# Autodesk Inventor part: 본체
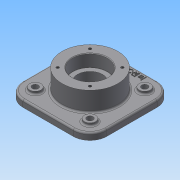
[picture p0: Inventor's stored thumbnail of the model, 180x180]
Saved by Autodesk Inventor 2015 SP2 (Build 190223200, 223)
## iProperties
Created: 2015-07
Part Number: 본체
Material: 일반
Document SubType Name: Modeling
Designer: AMC
Density: 1 g/cm^3
Appearance: 기본값
Author: AMC
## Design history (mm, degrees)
sketch "스케치1"
  geometry: L1 (-75, 75)-(75, 75); L2 (75, 75)-(75, -75); L3 (75, -75)-(-75, -75); L4 (-75, -75)-(-75, 75); L5 (-75, 75)-(75, -75); L6 (75, 75)-(-75, -75); 1 further point
  constraints: 12 end point, 2 midpoint, 2 parallel, 1 horizontal, 1 perpendicular
  dimensions: "d0" = 150 distance of L2.end L3.end; "d1" = 150 distance of L1.end L2.end
extrude "돌출1" new body sketch "스케치1" distance "d2" = 12; taper "d3" = 0 deg
sketch "스케치2"
  geometry: C1 r 50 at (0, 0); 1 further point
  constraints: 1 centre point, 1 coincident
  dimensions: "d4" = 100 diameter of C1
extrude "돌출2" join sketch "스케치2" distance "d5" = 47; taper "d7" = 0 deg; dims "d6" = 23, "d8" = 0
hole "구멍1" diameter "d11" = 45; stored, may be unused: countersink angle "d15" = 90 deg, drill point angle "d17" = 118 deg; dims "d9" = 10, "d10" = 10, "d12" = 6, "d13" = 62, "d14" = 22, "d16" = 8
hole "구멍2" diameter "d20" = 45; stored, may be unused: countersink angle "d24" = 90 deg, drill point angle "d26" = 118 deg; dims "d18" = 10, "d19" = 10, "d21" = 6, "d22" = 62, "d23" = 22, "d25" = 8
sketch "스케치3"
  geometry: L1 (0, 0)-(41, 0); L2 (0, 0)-(28.991, 28.991); A1 r 41 centre (0, 0) between (41, 0) and (28.991, 28.991); 2 further points
  constraints: 4 end point, 2 coincident, 2 point on circle, 1 centre point, 1 horizontal
  dimensions: "d27" = 82 diameter of A1; "d28" = 45 deg angle of L1 L2
hole "구멍3" sketch "스케치3" at (28.991, 28.991) diameter "d29" = 4.917; stored, may be unused: countersink angle "d33" = 90 deg, drill point angle "d35" = 118 deg; dims "d30" = 10, "d31" = 62, "d32" = 22, "d34" = 13
sketch "스케치4"
  geometry: L1 (0, 0)-(0, 41); L2 (0, 0)-(-28.991, 28.991); A1 r 41 centre (0, 0) between (0, 41) and (-28.991, 28.991); 2 further points
  constraints: 4 end point, 2 coincident, 2 point on circle, 1 centre point, 1 vertical
  dimensions: "d39" = 82 diameter of A1; "d40" = 45 deg angle of L1 L2
hole "구멍4" sketch "스케치4" at (-28.991, 28.991) diameter "d41" = 4.917; stored, may be unused: countersink angle "d45" = 90 deg, drill point angle "d47" = 118 deg; dims "d42" = 10, "d43" = 62, "d44" = 22, "d46" = 13
sketch "스케치5"
  geometry: L1 (-75, -75)-(-75, 75) reference; L2 (-75, 75)-(75, 75) reference; C1 r 10 at (-49, 49); C2 r 10 at (49, 49); C3 r 10 at (49, -49); C4 r 10 at (-49, -49); 5 further points
  constraints: 4 centre point, 4 coincident, 2 horizontal alignment, 2 vertical alignment
  dimensions: "d51" = 26 distance from line of L1 point (-49, 49); "d52" = 26 distance from line of L2 point (-49, 49); "d53" = 98 distance of point (49, 49) point (-49, 49); "d54" = 98 distance of point (-49, -49) point (-49, 49); "d55" = 20 diameter of C1; "d56" = 20 diameter of C2; "d57" = 20 diameter of C3; "d58" = 20 diameter of C4
extrude "돌출3" join sketch "스케치5" distance "d59" = 5; taper "d60" = 0 deg
hole "구멍5" diameter "d63" = 11; stored, may be unused: countersink angle "d67" = 90 deg, drill point angle "d69" = 118 deg; dims "d61" = 10, "d62" = 10, "d64" = 11, "d65" = 62, "d66" = 22, "d68" = 13
hole "구멍6" diameter "d72" = 11; stored, may be unused: countersink angle "d76" = 90 deg, drill point angle "d78" = 118 deg; dims "d70" = 10, "d71" = 10, "d73" = 11, "d74" = 62, "d75" = 22, "d77" = 13
hole "구멍7" diameter "d81" = 11; stored, may be unused: countersink angle "d85" = 90 deg, drill point angle "d87" = 118 deg; dims "d79" = 10, "d80" = 10, "d82" = 11, "d83" = 62, "d84" = 22, "d86" = 13
hole "구멍8" diameter "d90" = 11; stored, may be unused: countersink angle "d94" = 90 deg, drill point angle "d96" = 118 deg; dims "d88" = 10, "d89" = 10, "d91" = 11, "d92" = 62, "d93" = 22, "d95" = 13
fillet "모깎기1" dims "d97" = 30
fillet "모깎기2" dims "d98" = 3
fillet "모깎기3" dims "d99" = 3
fillet "모깎기4" dims "d100" = 0.3
chamfer "모따기1" distance "d101" = 1; stored, may be unused: second distance "d102" = 2, angle "d103" = 45 deg
sketch "스케치6"
  geometry: 2 further points
  constraints: 1 vertical alignment, 1 other
  dimensions: "d104" = 65 distance of point (0, 0) point (0, 65)
feature "엠보싱1" sketch "스케치6" dims "d0" = 150, "d1" = 150, "d105" = 1, "d106" = 0
node "솔리드1"
pattern_circular "원형 패턴1" dims angle "d37" = 360 deg
pattern_circular "원형 패턴2" dims angle "d49" = 360 deg
